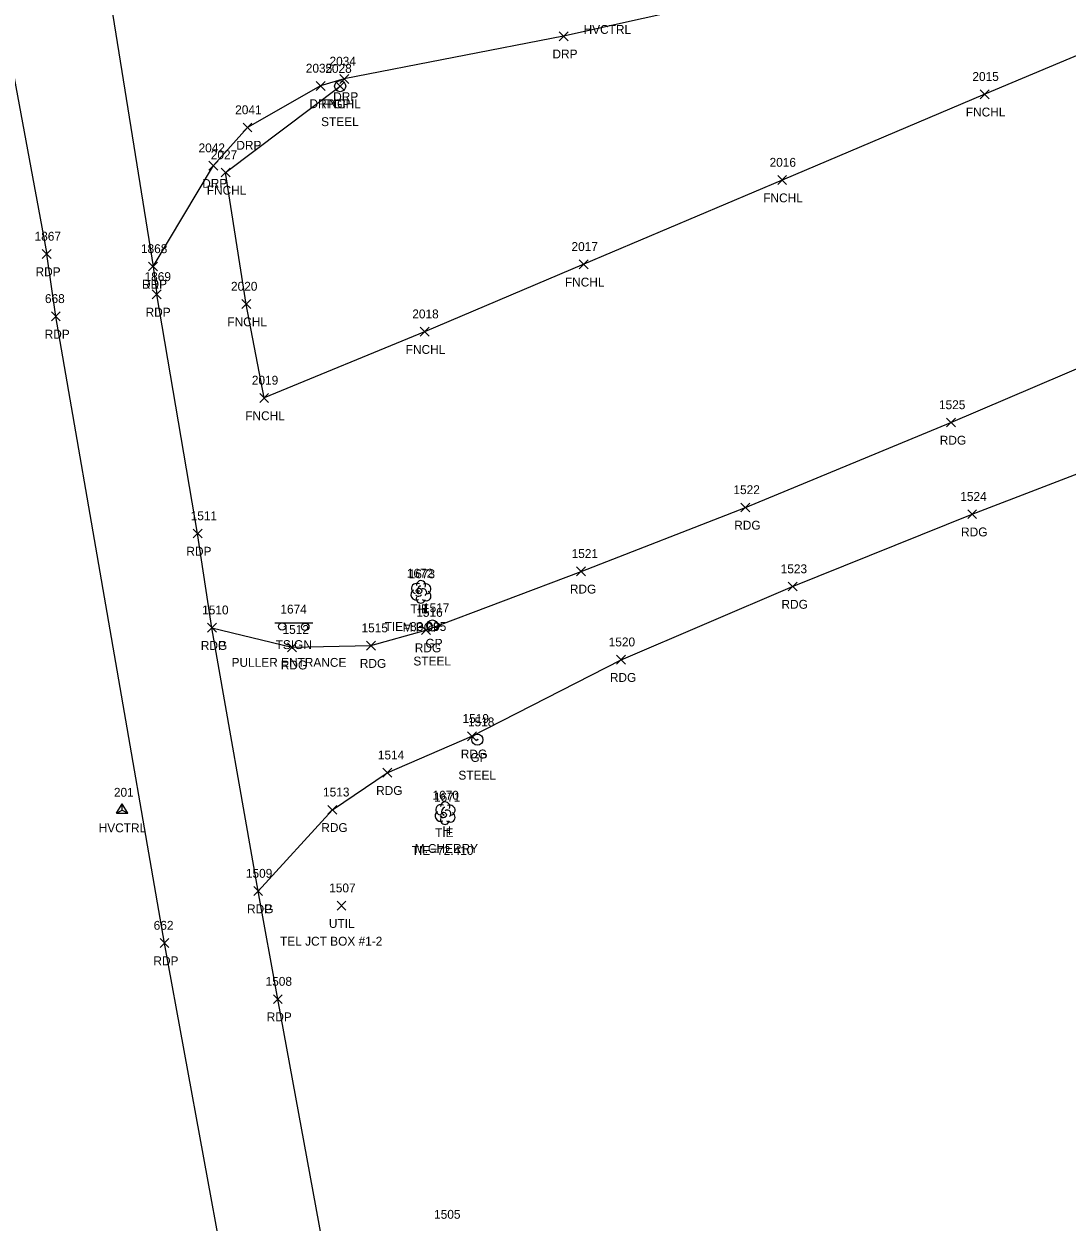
# Model space of a CAD drawing. Extents: x 1481523 to 1489083, y 884156 to 893756.
# Drawn here: x 1486651.1 to 1486886.1, y 887896.8 to 888166.7 of the extents above; entities that cross this region are included whole.
import ezdxf

# ---------------------------------------------------------------- set-up
doc = ezdxf.new("R2010")
doc.units = 0
for name, color, linetype in [('C_A', 7, 'Continuous'), ('C_C', 7, 'Continuous'), ('C_I', 7, 'Continuous'), ('CBP', 7, 'Continuous'), ('CPSM', 7, 'Continuous'), ('L_A', 7, 'Continuous'), ('L_C', 7, 'Continuous'), ('L_I', 7, 'Continuous'), ('L_TIC', 7, 'Continuous'), ('LFNC', 7, 'Continuous'), ('LTD', 7, 'Continuous'), ('P_A', 7, 'Continuous'), ('P_I', 7, 'Continuous'), ('P_TIC', 7, 'Continuous'), ('PET', 7, 'Continuous'), ('PEU', 7, 'Continuous'), ('R_A', 7, 'Continuous'), ('R_C', 7, 'Continuous'), ('R_I', 7, 'Continuous'), ('R_TIC', 7, 'Continuous'), ('RDP', 7, 'Continuous'), ('RGP', 7, 'Continuous'), ('S_A', 7, 'Continuous'), ('S_C', 7, 'Continuous'), ('S_I', 7, 'Continuous'), ('SSGN', 7, 'Continuous'), ('U_A', 7, 'Continuous'), ('U_C', 7, 'Continuous'), ('U_I', 7, 'Continuous'), ('UDEFAULT', 7, 'Continuous')]:
    doc.layers.add(name, color=color, linetype=linetype)

msp = doc.modelspace()

# ---------------------------------------------------------------- linework, layer by layer
at = {"layer": 'CBP'}
for centre, radius in [((1486740.07, 888038.92), 0.625), ((1486740.07, 888038.92), 0.0833), ((1486745.62, 887988.47), 0.625), ((1486745.62, 887988.47), 0.0833)]:
    msp.add_circle(centre, radius, dxfattribs=at)
at = {"layer": 'CPSM'}
for p, q in [((1486671.96, 887988.85), (1486673.21, 887991.01)), ((1486671.96, 887988.85), (1486673.21, 887989.57)), ((1486674.46, 887988.85), (1486673.21, 887991.01)), ((1486673.21, 887989.57), (1486673.21, 887991.01)), ((1486673.21, 887989.57), (1486673.21, 887989.57)), ((1486673.21, 887989.57), (1486674.46, 887988.85)), ((1486671.96, 887988.85), (1486674.46, 887988.85))]:
    msp.add_line(p, q, dxfattribs=at)
at = {"layer": 'L_TIC'}
for points in [[(1486721.31, 888151.64), (1486723.31, 888153.64)], [(1486723.31, 888151.64), (1486721.31, 888153.64)], [(1486866.52, 888149.81), (1486868.52, 888151.81)], [(1486868.52, 888149.81), (1486866.52, 888151.81)], [(1486695.51, 888132.19), (1486697.51, 888134.19)], [(1486697.51, 888132.19), (1486695.51, 888134.19)], [(1486820.88, 888130.48), (1486822.88, 888132.48)], [(1486822.88, 888130.48), (1486820.88, 888132.48)], [(1486776.19, 888111.51), (1486778.19, 888113.51)], [(1486778.19, 888111.51), (1486776.19, 888113.51)], [(1486700.15, 888102.56), (1486702.15, 888104.56)], [(1486702.15, 888102.56), (1486700.15, 888104.56)], [(1486740.33, 888096.33), (1486742.33, 888098.33)], [(1486742.33, 888096.33), (1486740.33, 888098.33)], [(1486704.19, 888081.4), (1486706.19, 888083.4)], [(1486706.19, 888081.4), (1486704.19, 888083.4)]]:
    msp.add_lwpolyline(points, dxfattribs=at)
at = {"layer": 'LFNC'}
msp.add_lwpolyline([(1487123.63, 888696.4), (1487124.91, 888638.27), (1487126.15, 888568.63), (1487127.36, 888492.8), (1487107.41, 888449.36), (1487090.77, 888413.6), (1487074.34, 888378.07), (1487054.02, 888334.46), (1487033.84, 888290.91), (1487013.45, 888247.02), (1487001.64, 888221.58), (1486993.21, 888204.38), (1486939.48, 888181.13), (1486867.52, 888150.81), (1486821.88, 888131.48), (1486777.19, 888112.51), (1486741.33, 888097.33), (1486705.19, 888082.4), (1486701.15, 888103.56), (1486696.51, 888133.19), (1486722.31, 888152.64)], dxfattribs=at)
at = {"layer": 'LTD'}
for p, q in [((1486740.48, 888038.78), (1486740.48, 888038.78)), ((1486740.48, 888038.78), (1486740.48, 888038.78)), ((1486745.93, 887988.92), (1486745.93, 887988.92)), ((1486745.93, 887988.92), (1486745.93, 887988.92))]:
    msp.add_line(p, q, dxfattribs=at)
for centre in [(1486740.53, 888040.21), (1486745.98, 887990.36)]:
    msp.add_arc(centre, 1.05, 335.5272, 180.9563, dxfattribs=at)
for centre, major_axis, ratio, start_param, end_param in [((1486739.69, 888039.44), (1.21, -0.51), 0.895232, 1.570796, 4.712389), ((1486741.52, 888039.36), (-1.14, -0.48), 0.949671, 1.570796, 4.712389), ((1486739.4, 888038.07), (0.58, -1.04), 0.959034, 3.141593, 6.283185), ((1486740.48, 888037.28), (0.26, 1.06), 0.942809, 1.570796, 4.712389), ((1486740.02, 888038.03), (-0.625, -0.083), 0.423636, 0, 3.141593), ((1486740.27, 888039.23), (-0.208, -0.792), 0.645439, 3.141593, 6.283185), ((1486740.98, 888038.61), (-0.5, 0.667), 0.989748, 3.141593, 6.283185), ((1486741.48, 888037.94), (-1.09, 0.79), 0.841452, 1.570796, 4.712389), ((1486744.85, 887988.21), (0.58, -1.04), 0.959034, 3.141593, 6.283185), ((1486745.14, 887989.59), (1.21, -0.51), 0.895232, 1.570796, 4.712389), ((1486745.72, 887989.38), (-0.208, -0.792), 0.645439, 3.141593, 6.283185), ((1486746.43, 887988.76), (-0.5, 0.667), 0.989748, 3.141593, 6.283185), ((1486746.93, 887988.09), (-1.09, 0.79), 0.841452, 1.570796, 4.712389), ((1486746.97, 887989.51), (-1.14, -0.48), 0.949671, 1.570796, 4.712389), ((1486745.93, 887987.42), (0.26, 1.06), 0.942809, 1.570796, 4.712389), ((1486745.48, 887988.17), (-0.625, -0.083), 0.423636, 0, 3.141593)]:
    msp.add_ellipse(centre, major_axis=major_axis, ratio=ratio, start_param=start_param, end_param=end_param, dxfattribs=at)
at = {"layer": 'P_TIC'}
for points in [[(1486655.21, 888113.83), (1486657.21, 888115.83)], [(1486657.21, 888113.83), (1486655.21, 888115.83)], [(1486679.17, 888111.03), (1486681.17, 888113.03)], [(1486681.17, 888111.03), (1486679.17, 888113.03)], [(1486679.99, 888104.73), (1486681.99, 888106.73)], [(1486681.99, 888104.73), (1486679.99, 888106.73)], [(1486679.99, 888104.73), (1486681.99, 888106.73)], [(1486681.99, 888104.73), (1486679.99, 888106.73)], [(1486657.25, 888099.78), (1486659.25, 888101.78)], [(1486659.25, 888099.78), (1486657.25, 888101.78)], [(1486858.9, 888075.88), (1486860.9, 888077.88)], [(1486860.9, 888075.88), (1486858.9, 888077.88)], [(1486812.61, 888056.74), (1486814.61, 888058.74)], [(1486814.61, 888056.74), (1486812.61, 888058.74)], [(1486863.7, 888055.22), (1486865.7, 888057.22)], [(1486865.7, 888055.22), (1486863.7, 888057.22)], [(1486689.19, 888050.87), (1486691.19, 888052.87)], [(1486691.19, 888050.87), (1486689.19, 888052.87)], [(1486689.19, 888050.87), (1486691.19, 888052.87)], [(1486691.19, 888050.87), (1486689.19, 888052.87)], [(1486775.57, 888042.35), (1486777.57, 888044.35)], [(1486777.57, 888042.35), (1486775.57, 888044.35)], [(1486823.24, 888038.92), (1486825.24, 888040.92)], [(1486825.24, 888038.92), (1486823.24, 888040.92)], [(1486692.43, 888029.65), (1486694.43, 888031.65)], [(1486694.43, 888029.65), (1486692.43, 888031.65)], [(1486692.43, 888029.65), (1486694.43, 888031.65)], [(1486694.43, 888029.65), (1486692.43, 888031.65)], [(1486740.64, 888029.11), (1486742.64, 888031.11)], [(1486742.64, 888029.11), (1486740.64, 888031.11)], [(1486710.45, 888025.25), (1486712.45, 888027.25)], [(1486712.45, 888025.25), (1486710.45, 888027.25)], [(1486728.25, 888025.61), (1486730.25, 888027.61)], [(1486730.25, 888025.61), (1486728.25, 888027.61)], [(1486784.58, 888022.44), (1486786.58, 888024.44)], [(1486786.58, 888022.44), (1486784.58, 888024.44)], [(1486751, 888005.2), (1486753, 888007.2)], [(1486753, 888005.2), (1486751, 888007.2)], [(1486731.92, 887996.98), (1486733.92, 887998.98)], [(1486733.92, 887996.98), (1486731.92, 887998.98)], [(1486719.57, 887988.63), (1486721.57, 887990.63)], [(1486721.57, 887988.63), (1486719.57, 887990.63)], [(1486702.84, 887970.32), (1486704.84, 887972.32)], [(1486704.84, 887970.32), (1486702.84, 887972.32)], [(1486702.84, 887970.32), (1486704.84, 887972.32)], [(1486704.84, 887970.32), (1486702.84, 887972.32)], [(1486681.75, 887958.61), (1486683.75, 887960.61)], [(1486683.75, 887958.61), (1486681.75, 887960.61)], [(1486707.28, 887945.99), (1486709.28, 887947.99)], [(1486709.28, 887945.99), (1486707.28, 887947.99)]]:
    msp.add_lwpolyline(points, dxfattribs=at)
at = {"layer": 'PET'}
for points in [[(1486482.46, 889213.8), (1486493.22, 889156.8), (1486512.17, 889057.76), (1486527.58, 888974.51), (1486542.53, 888889.08), (1486553.79, 888825.37), (1486565.07, 888760.91), (1486577.19, 888690.78), (1486591.4, 888610.57), (1486602.78, 888547.25), (1486614.23, 888481.5), (1486627.06, 888409.28), (1486638.94, 888342.58), (1486654.61, 888252.22), (1486669.1, 888181.27), (1486680.17, 888112.03), (1486680.99, 888105.73)], [(1486459.06, 889211.36), (1486470.75, 889147.47), (1486504.42, 888970.47), (1486519.24, 888886.05), (1486530.77, 888821.38), (1486542.03, 888758.69), (1486549.22, 888711.97), (1486553.24, 888690.65), (1486568.55, 888607.7), (1486579.98, 888541.46), (1486590.64, 888481.54), (1486600.71, 888424.31), (1486604.32, 888404.42), (1486616.77, 888334.61), (1486631.96, 888248.32), (1486646.36, 888167.9), (1486656.21, 888114.83)], [(1486658.25, 888100.78), (1486656.21, 888114.83)], [(1486690.19, 888051.87), (1486680.99, 888105.73)], [(1487623.03, 886396.68), (1487614.71, 886412.68), (1487509.53, 886558.33), (1487399.2, 886710.79), (1487304.98, 886841.59), (1487249.25, 886918.99), (1487138.6, 887072.86), (1487086.89, 887144.79), (1486969.76, 887307.16), (1486903.3, 887400.42), (1486868.78, 887451.35), (1486836.4, 887503.18), (1486808.87, 887552.94), (1486786.32, 887598.75), (1486760.43, 887659.94), (1486738.28, 887720.05), (1486718.2, 887787.22), (1486705.95, 887838.78), (1486696.04, 887887.03), (1486682.75, 887959.61), (1486658.25, 888100.78)], [(1486708.28, 887946.99), (1486703.84, 887971.32), (1486693.43, 888030.65), (1486690.19, 888051.87)], [(1486718.95, 887888.93), (1486708.28, 887946.99)]]:
    msp.add_lwpolyline(points, dxfattribs=at)
at = {"layer": 'PEU'}
for points in [[(1486693.43, 888030.65), (1486711.45, 888026.25), (1486729.25, 888026.61), (1486741.64, 888030.11), (1486776.57, 888043.35), (1486813.61, 888057.74), (1486859.9, 888076.88), (1486905.09, 888096.2), (1486933.17, 888108.11), (1486991.44, 888135.23), (1487027.3, 888151.91), (1487061.93, 888172.65), (1487100.02, 888202.76), (1487134.5, 888235.55), (1487174.13, 888267.94)], [(1486703.84, 887971.32), (1486720.57, 887989.63), (1486732.92, 887997.98), (1486752, 888006.2), (1486785.58, 888023.44), (1486824.24, 888039.92), (1486864.7, 888056.22), (1486913.32, 888074.9), (1486944.19, 888087.45), (1487001.42, 888113.78), (1487037.5, 888132.44), (1487077.83, 888154.12), (1487114.03, 888185.38), (1487147.32, 888221.55), (1487184.59, 888252.66)]]:
    msp.add_lwpolyline(points, dxfattribs=at)
at = {"layer": 'R_TIC'}
for points in [[(1486771.66, 888162.88), (1486773.66, 888164.88)], [(1486773.66, 888162.88), (1486771.66, 888164.88)], [(1486716.91, 888151.68), (1486718.91, 888153.68)], [(1486718.91, 888151.68), (1486716.91, 888153.68)], [(1486722.25, 888153.26), (1486724.25, 888155.26)], [(1486724.25, 888153.26), (1486722.25, 888155.26)], [(1486700.43, 888142.32), (1486702.43, 888144.32)], [(1486702.43, 888142.32), (1486700.43, 888144.32)], [(1486692.75, 888133.74), (1486694.75, 888135.74)], [(1486694.75, 888133.74), (1486692.75, 888135.74)], [(1486692.75, 888133.74), (1486694.75, 888135.74)], [(1486694.75, 888133.74), (1486692.75, 888135.74)], [(1486679.17, 888111.03), (1486681.17, 888113.03)], [(1486681.17, 888111.03), (1486679.17, 888113.03)]]:
    msp.add_lwpolyline(points, dxfattribs=at)
at = {"layer": 'RDP'}
for points in [[(1486959.85, 888365.95), (1486963.01, 888350.2), (1486966.58, 888328.39), (1486977.82, 888267.82), (1486986.38, 888222.13), (1486988.25, 888212.61), (1486961.42, 888207.24), (1486873.46, 888185.48), (1486827.16, 888176.05), (1486772.66, 888163.88), (1486723.25, 888154.26), (1486717.91, 888152.68), (1486701.43, 888143.32), (1486693.75, 888134.74)], [(1486680.17, 888112.03), (1486693.75, 888134.74)]]:
    msp.add_lwpolyline(points, dxfattribs=at)
at = {"layer": 'RGP'}
for p, q in [((1486722.31, 888152.64), (1486722.31, 888152.64)), ((1486743.09, 888031.14), (1486743.09, 888031.14)), ((1486753.23, 888005.43), (1486753.23, 888005.43))]:
    msp.add_line(p, q, dxfattribs=at)
for centre, radius in [((1486722.31, 888152.64), 1.25), ((1486722.31, 888152.64), 0.0833), ((1486743.09, 888031.14), 1.25), ((1486743.09, 888031.14), 0.0833), ((1486753.23, 888005.43), 1.25), ((1486753.23, 888005.43), 0.0833)]:
    msp.add_circle(centre, radius, dxfattribs=at)
at = {"layer": 'SSGN'}
for p, q in [((1486707.57, 888031.76), (1486716.17, 888031.76)), ((1486711.59, 888030.86), (1486711.59, 888030.86))]:
    msp.add_line(p, q, dxfattribs=at)
for centre in [(1486709.23, 888030.93), (1486714.45, 888030.86)]:
    msp.add_circle(centre, 0.833, dxfattribs=at)
at = {"layer": 'UDEFAULT'}
for points in [[(1486721.61, 887967.03), (1486723.61, 887969.03)], [(1486723.61, 887967.03), (1486721.61, 887969.03)]]:
    msp.add_lwpolyline(points, dxfattribs=at)

# ---------------------------------------------------------------- texts
at = {"layer": 'C_A'}
for s, p in [('HVCTRL', (1486777.15, 888164.42)), ('TIE', (1486738.15, 888033.92)), ('HVCTRL', (1486667.91, 887984.57)), ('TIE', (1486743.7, 887983.47))]:
    msp.add_text(s, height=2, dxfattribs=at).set_placement(p)
at = {"layer": 'C_C'}
for s, p in [('TIE=83.095', (1486732.32, 888029.92)), ('TIE=72.410', (1486738.43, 887979.47))]:
    msp.add_text(s, height=2, dxfattribs=at).set_placement(p)
at = {"layer": 'C_I'}
for s, p in [('1672', (1486737.33, 888041.92)), ('201', (1486671.34, 887992.57)), ('1671', (1486743.44, 887991.47))]:
    msp.add_text(s, height=2, dxfattribs=at).set_placement(p)
at = {"layer": 'L_A'}
for s, p in [('FNCHL', (1486718.05, 888147.64)), ('FNCHL', (1486863.26, 888145.81)), ('FNCHL', (1486692.26, 888128.19)), ('FNCHL', (1486817.62, 888126.48)), ('FNCHL', (1486772.94, 888107.51)), ('FNCHL', (1486696.9, 888098.56)), ('FNCHL', (1486737.08, 888092.33)), ('FNCHL', (1486700.93, 888077.4)), ('H', (1486739.91, 888033.78)), ('H', (1486745.37, 887983.92))]:
    msp.add_text(s, height=2, dxfattribs=at).set_placement(p)
at = {"layer": 'L_C'}
for s, p in [('M.POP', (1486736.38, 888029.78)), ('M.CHERRY', (1486739.11, 887979.92))]:
    msp.add_text(s, height=2, dxfattribs=at).set_placement(p)
at = {"layer": 'L_I'}
for s, p in [('2028', (1486718.97, 888155.64)), ('2015', (1486864.74, 888153.81)), ('2027', (1486693.17, 888136.19)), ('2016', (1486819.05, 888134.48)), ('2017', (1486774.42, 888115.51)), ('2020', (1486697.72, 888106.56)), ('2018', (1486738.56, 888100.33)), ('2019', (1486702.41, 888085.4)), ('1673', (1486737.74, 888041.78)), ('1670', (1486743.11, 887991.92))]:
    msp.add_text(s, height=2, dxfattribs=at).set_placement(p)
at = {"layer": 'P_A'}
for s, p in [('RDP', (1486653.69, 888109.83)), ('RDP', (1486677.66, 888107.03)), ('RDP', (1486678.48, 888100.73)), ('RDP', (1486678.48, 888100.73)), ('RDP', (1486655.74, 888095.78)), ('RDG', (1486857.39, 888071.88)), ('RDG', (1486811.09, 888052.74)), ('RDG', (1486862.19, 888051.22)), ('RDP', (1486687.67, 888046.87)), ('RDP', (1486687.67, 888046.87)), ('RDG', (1486774.06, 888038.35)), ('RDG', (1486821.73, 888034.92)), ('RDG', (1486690.92, 888025.65)), ('RDP', (1486690.92, 888025.65)), ('RDG', (1486739.12, 888025.11)), ('RDG', (1486708.94, 888021.25)), ('RDG', (1486726.74, 888021.61)), ('RDG', (1486783.07, 888018.44)), ('RDG', (1486749.49, 888001.2)), ('RDG', (1486730.41, 887992.98)), ('RDG', (1486718.06, 887984.63)), ('RDG', (1486701.33, 887966.32)), ('RDP', (1486701.33, 887966.32)), ('RDP', (1486680.24, 887954.61)), ('RDP', (1486705.77, 887941.99))]:
    msp.add_text(s, height=2, dxfattribs=at).set_placement(p)
at = {"layer": 'P_I'}
for s, p in [('1867', (1486653.47, 888117.83)), ('1868', (1486677.43, 888115.03)), ('1869', (1486678.24, 888108.73)), ('1869', (1486678.24, 888108.73)), ('668', (1486655.8, 888103.78)), ('1525', (1486857.21, 888079.88)), ('1522', (1486810.91, 888060.74)), ('1524', (1486862.01, 888059.22)), ('1511', (1486688.63, 888054.87)), ('1511', (1486688.63, 888054.87)), ('1521', (1486774.45, 888046.35)), ('1523', (1486821.55, 888042.92)), ('1510', (1486691.22, 888033.65)), ('1510', (1486691.22, 888033.65)), ('1516', (1486739.46, 888033.11)), ('1512', (1486709.33, 888029.25)), ('1515', (1486727.12, 888029.61)), ('1520', (1486782.8, 888026.44)), ('1519', (1486749.87, 888009.2)), ('1514', (1486730.8, 888000.98)), ('1513', (1486718.45, 887992.63)), ('1509', (1486701.07, 887974.32)), ('1509', (1486701.07, 887974.32)), ('662', (1486680.3, 887962.61)), ('1508', (1486705.51, 887949.99))]:
    msp.add_text(s, height=2, dxfattribs=at).set_placement(p)
at = {"layer": 'R_A'}
for s, p in [('DRP', (1486770.14, 888158.88)), ('DRP', (1486720.74, 888149.26)), ('DRP', (1486715.4, 888147.68)), ('GP', (1486720.74, 888147.64)), ('DRP', (1486698.92, 888138.32)), ('DRP', (1486691.23, 888129.74)), ('DRP', (1486691.23, 888129.74)), ('DRP', (1486677.66, 888107.03)), ('GP', (1486741.53, 888026.14)), ('GP', (1486751.66, 888000.43))]:
    msp.add_text(s, height=2, dxfattribs=at).set_placement(p)
at = {"layer": 'R_C'}
for p in [(1486718.02, 888143.64), (1486738.81, 888022.14), (1486748.95, 887996.43)]:
    msp.add_text('STEEL', height=2, dxfattribs=at).set_placement(p)
at = {"layer": 'R_I'}
for s, p in [('2034', (1486719.91, 888157.26)), ('2035', (1486714.57, 888155.68)), ('2028', (1486718.97, 888155.64)), ('2041', (1486698.66, 888146.32)), ('2042', (1486690.41, 888137.74)), ('2042', (1486690.41, 888137.74)), ('1868', (1486677.43, 888115.03)), ('1517', (1486740.97, 888034.14)), ('1518', (1486751.1, 888008.43))]:
    msp.add_text(s, height=2, dxfattribs=at).set_placement(p)
at = {"layer": 'S_A'}
msp.add_text('TSIGN', height=2, dxfattribs=at).set_placement((1486707.77, 888025.84))
at = {"layer": 'S_C'}
msp.add_text('PULLER ENTRANCE', height=2, dxfattribs=at).set_placement((1486697.85, 888021.84))
at = {"layer": 'S_I'}
msp.add_text('1674', height=2, dxfattribs=at).set_placement((1486708.85, 888033.84))
at = {"layer": 'U_A'}
msp.add_text('UTIL', height=2, dxfattribs=at).set_placement((1486719.77, 887963.03))
at = {"layer": 'U_C'}
msp.add_text('TEL JCT BOX #1-2', height=2, dxfattribs=at).set_placement((1486708.77, 887959.03))
at = {"layer": 'U_I'}
for s, p in [('1507', (1486719.84, 887971.03)), ('1505', (1486743.47, 887897.51))]:
    msp.add_text(s, height=2, dxfattribs=at).set_placement(p)

doc.saveas('drawing.dxf')
